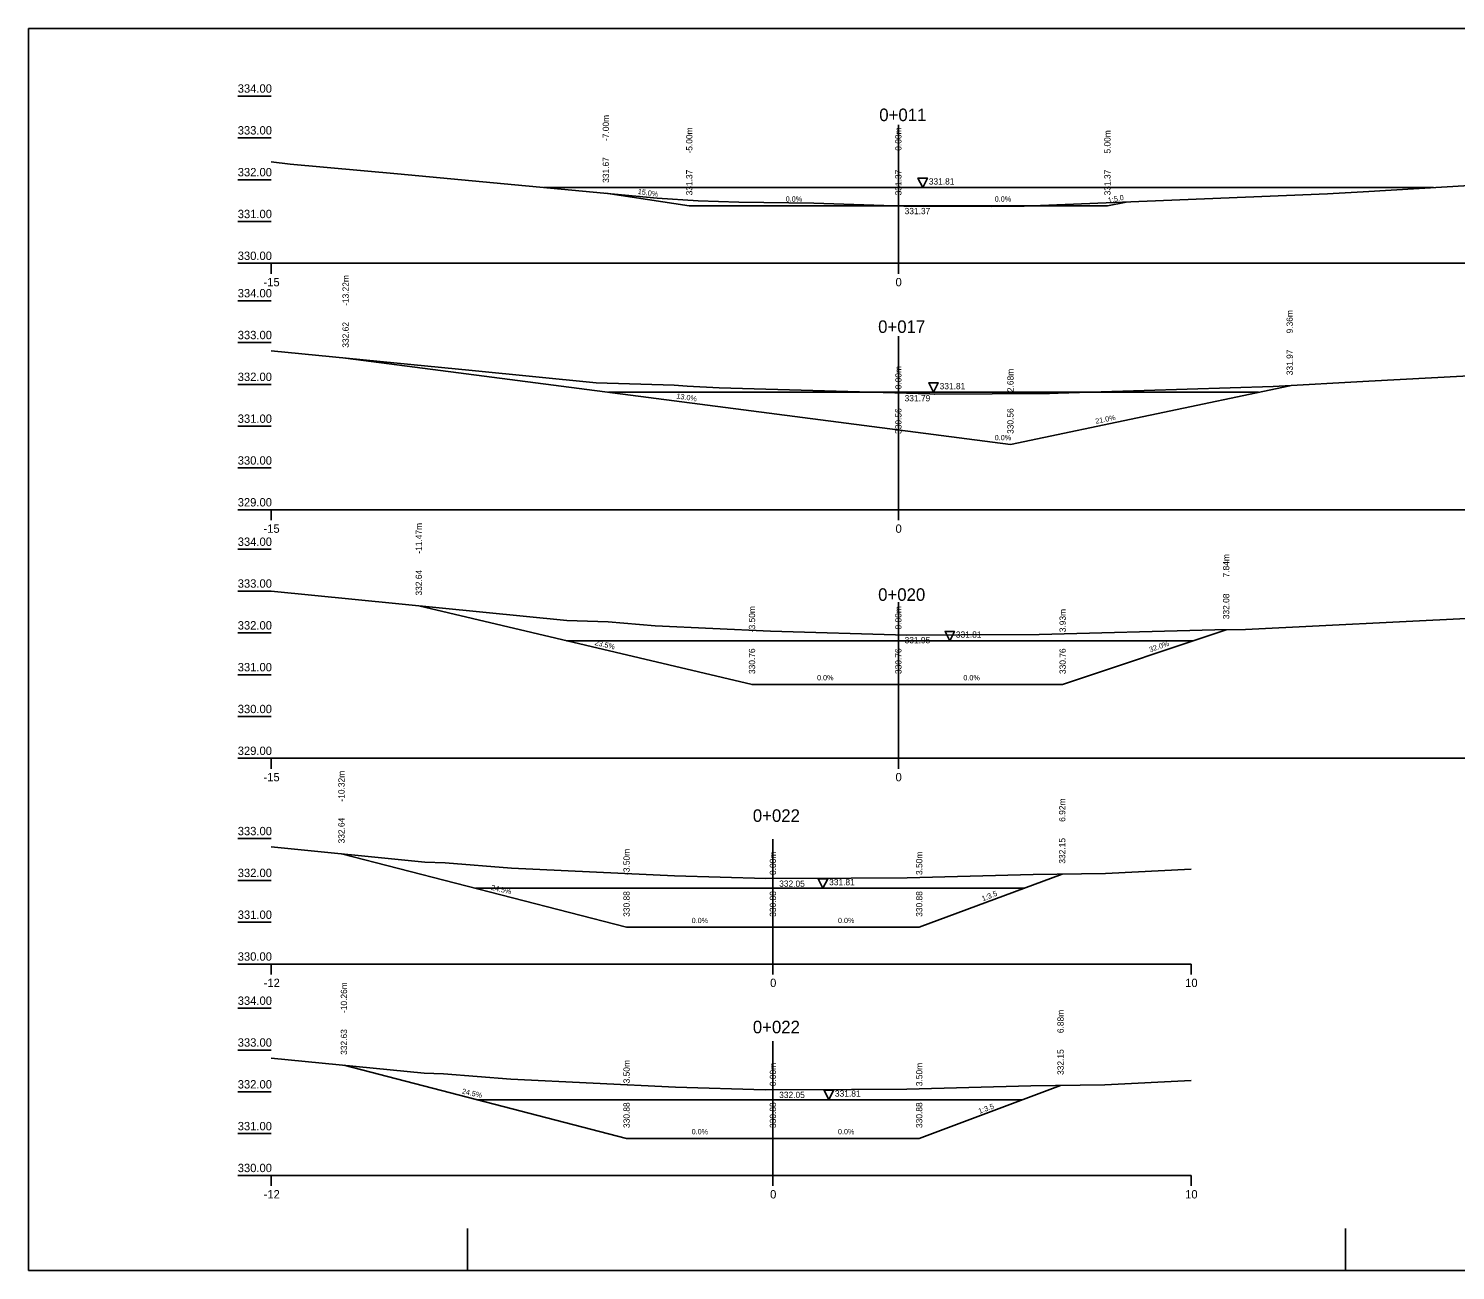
# Model space of a CAD drawing. Extents: x -557924.8 to -557872.3, y -1163725.6 to -1163695.9.
# Drawn here: x -557924.75 to -557890.63, y -1163725.55 to -1163695.85 of the extents above; entities that cross this region are included whole.
import ezdxf

# ---------------------------------------------------------------- set-up
doc = ezdxf.new("R2010")
doc.units = 0
for name, color, linetype in [('16', 7, 'Continuous'), ('21', 7, 'Continuous'), ('28', 7, 'Continuous'), ('59', 7, 'Continuous'), ('Body pricny rez', 7, 'Continuous'), ('Popis pricneho profilu', 7, 'Continuous')]:
    doc.layers.add(name, color=color, linetype=linetype)

msp = doc.modelspace()

# ---------------------------------------------------------------- linework, layer by layer
for p, q in [((-557872.255, -1163695.855), (-557924.755, -1163695.855)), ((-557924.755, -1163695.855), (-557924.755, -1163725.555)), ((-557914.255, -1163725.555), (-557914.255, -1163724.555)), ((-557893.255, -1163725.555), (-557893.255, -1163724.555)), ((-557924.755, -1163725.555), (-557872.255, -1163725.555))]:
    msp.add_line(p, q)
for points in [[(-557918.951, -1163699.04), (-557918.5, -1163699.102), (-557915.931, -1163699.332), (-557909.723, -1163699.909), (-557908.742, -1163699.977), (-557907.763, -1163700.007), (-557905.975, -1163700.03), (-557903.818, -1163700.099), (-557901.717, -1163700.109), (-557900.944, -1163700.106), (-557893.687, -1163699.806), (-557893.547, -1163699.801), (-557892.834, -1163699.759), (-557888.951, -1163699.526)], [(-557912.421, -1163699.658), (-557891.151, -1163699.658)], [(-557910.947, -1163699.795), (-557908.951, -1163700.094), (-557903.951, -1163700.094), (-557898.951, -1163700.094), (-557898.505, -1163700.005)], [(-557908.951, -1163700.094), (-557910.947, -1163699.795)], [(-557908.951, -1163700.094), (-557910.947, -1163699.795)], [(-557903.951, -1163700.094), (-557908.951, -1163700.094)], [(-557903.951, -1163700.094), (-557908.951, -1163700.094)], [(-557903.951, -1163700.094), (-557898.951, -1163700.094)], [(-557903.951, -1163700.094), (-557898.951, -1163700.094)], [(-557898.951, -1163700.094), (-557898.505, -1163700.005)], [(-557898.951, -1163700.094), (-557898.505, -1163700.005)], [(-557918.951, -1163703.563), (-557914.142, -1163704.032), (-557911.18, -1163704.326), (-557909.313, -1163704.385), (-557909.001, -1163704.41), (-557908.235, -1163704.447), (-557903.194, -1163704.592), (-557903.088, -1163704.595), (-557903.08, -1163704.595), (-557900.337, -1163704.586), (-557900.125, -1163704.577), (-557894.989, -1163704.419), (-557892.701, -1163704.285), (-557888.951, -1163704.089)], [(-557917.171, -1163703.737), (-557901.271, -1163705.8)], [(-557901.271, -1163705.8), (-557894.591, -1163704.396)], [(-557910.884, -1163704.553), (-557895.336, -1163704.553)], [(-557918.951, -1163709.313), (-557911.88, -1163710.015), (-557910.889, -1163710.046), (-557909.765, -1163710.137), (-557907.01, -1163710.268), (-557903.744, -1163710.362), (-557902.449, -1163710.356), (-557900.581, -1163710.35), (-557896.385, -1163710.235), (-557895.647, -1163710.225), (-557890.2, -1163709.956), (-557888.951, -1163709.891)], [(-557903.951, -1163711.542), (-557907.451, -1163711.542), (-557915.421, -1163709.664)], [(-557900.021, -1163711.542), (-557896.111, -1163710.231)], [(-557911.889, -1163710.496), (-557896.901, -1163710.496)], [(-557903.951, -1163711.542), (-557907.451, -1163711.542)], [(-557903.951, -1163711.542), (-557900.451, -1163711.542)], [(-557903.951, -1163711.542), (-557900.021, -1163711.542)], [(-557918.951, -1163715.425), (-557915.28, -1163715.789), (-557914.791, -1163715.805), (-557913.202, -1163715.932), (-557909.308, -1163716.118), (-557907.124, -1163716.181), (-557905.082, -1163716.172), (-557903.742, -1163716.167), (-557900.73, -1163716.085), (-557898.999, -1163716.062), (-557896.951, -1163715.961)], [(-557906.951, -1163717.347), (-557910.451, -1163717.347), (-557917.271, -1163715.592)], [(-557903.451, -1163717.347), (-557900.031, -1163716.076)], [(-557914.068, -1163716.416), (-557900.947, -1163716.416)], [(-557906.951, -1163717.347), (-557910.451, -1163717.347)], [(-557906.951, -1163717.347), (-557903.451, -1163717.347)], [(-557906.951, -1163717.347), (-557903.451, -1163717.347)], [(-557918.951, -1163720.477), (-557915.296, -1163720.839), (-557914.826, -1163720.854), (-557913.219, -1163720.983), (-557909.281, -1163721.171), (-557907.139, -1163721.233), (-557905.068, -1163721.224), (-557903.748, -1163721.219), (-557900.782, -1163721.138), (-557899.013, -1163721.114), (-557896.951, -1163721.013)], [(-557906.951, -1163722.398), (-557910.451, -1163722.398), (-557917.211, -1163720.649)], [(-557903.451, -1163722.398), (-557900.071, -1163721.129)], [(-557914.032, -1163721.472), (-557900.985, -1163721.472)], [(-557906.951, -1163722.398), (-557910.451, -1163722.398)], [(-557906.951, -1163722.398), (-557903.451, -1163722.398)], [(-557906.951, -1163722.398), (-557903.451, -1163722.398)]]:
    msp.add_lwpolyline(points)
for points in [[(-557903.369, -1163699.658), (-557903.482, -1163699.433), (-557903.257, -1163699.433)], [(-557903.11, -1163704.553), (-557903.222, -1163704.328), (-557902.997, -1163704.328)], [(-557902.722, -1163710.496), (-557902.834, -1163710.271), (-557902.609, -1163710.271)], [(-557905.754, -1163716.416), (-557905.866, -1163716.191), (-557905.641, -1163716.191)], [(-557905.614, -1163721.472), (-557905.727, -1163721.247), (-557905.502, -1163721.247)]]:
    msp.add_lwpolyline(points, close=True)
at = {"layer": '16'}
for p, q in [((-557918.951, -1163701.469), (-557888.951, -1163701.469)), ((-557918.951, -1163707.364), (-557888.951, -1163707.364)), ((-557918.951, -1163713.307), (-557888.951, -1163713.307)), ((-557918.951, -1163718.227), (-557896.951, -1163718.227)), ((-557918.951, -1163723.283), (-557896.951, -1163723.283))]:
    msp.add_line(p, q, dxfattribs=at)
at = {"layer": '21'}
for p, q in [((-557919.751, -1163697.469), (-557918.951, -1163697.469)), ((-557919.751, -1163698.469), (-557918.951, -1163698.469)), ((-557919.751, -1163699.469), (-557918.951, -1163699.469)), ((-557919.751, -1163700.469), (-557918.951, -1163700.469)), ((-557919.751, -1163701.469), (-557918.951, -1163701.469)), ((-557919.751, -1163702.364), (-557918.951, -1163702.364)), ((-557919.751, -1163703.364), (-557918.951, -1163703.364)), ((-557919.751, -1163704.364), (-557918.951, -1163704.364)), ((-557919.751, -1163705.364), (-557918.951, -1163705.364)), ((-557919.751, -1163706.364), (-557918.951, -1163706.364)), ((-557919.751, -1163707.364), (-557918.951, -1163707.364)), ((-557919.751, -1163708.307), (-557918.951, -1163708.307)), ((-557919.751, -1163709.307), (-557918.951, -1163709.307)), ((-557919.751, -1163710.307), (-557918.951, -1163710.307)), ((-557919.751, -1163711.307), (-557918.951, -1163711.307)), ((-557919.751, -1163712.307), (-557918.951, -1163712.307)), ((-557919.751, -1163713.307), (-557918.951, -1163713.307)), ((-557919.751, -1163715.227), (-557918.951, -1163715.227)), ((-557919.751, -1163716.227), (-557918.951, -1163716.227)), ((-557919.751, -1163717.227), (-557918.951, -1163717.227)), ((-557919.751, -1163718.227), (-557918.951, -1163718.227)), ((-557919.751, -1163719.283), (-557918.951, -1163719.283)), ((-557919.751, -1163720.283), (-557918.951, -1163720.283)), ((-557919.751, -1163721.283), (-557918.951, -1163721.283)), ((-557919.751, -1163722.283), (-557918.951, -1163722.283)), ((-557919.751, -1163723.283), (-557918.951, -1163723.283))]:
    msp.add_line(p, q, dxfattribs=at)
at = {"layer": '28'}
for p, q in [((-557903.951, -1163698.158), (-557903.951, -1163701.469)), ((-557903.951, -1163703.212), (-557903.951, -1163707.364)), ((-557903.951, -1163709.574), (-557903.951, -1163713.307)), ((-557906.951, -1163715.24), (-557906.951, -1163718.227)), ((-557906.951, -1163720.069), (-557906.951, -1163723.283))]:
    msp.add_line(p, q, dxfattribs=at)
at = {"layer": '59'}
for p, q in [((-557918.951, -1163701.719), (-557918.951, -1163701.469)), ((-557903.951, -1163701.719), (-557903.951, -1163701.469)), ((-557918.951, -1163707.614), (-557918.951, -1163707.364)), ((-557903.951, -1163707.614), (-557903.951, -1163707.364)), ((-557918.951, -1163713.557), (-557918.951, -1163713.307)), ((-557903.951, -1163713.557), (-557903.951, -1163713.307)), ((-557918.951, -1163718.477), (-557918.951, -1163718.227)), ((-557906.951, -1163718.477), (-557906.951, -1163718.227)), ((-557896.951, -1163718.477), (-557896.951, -1163718.227)), ((-557918.951, -1163723.533), (-557918.951, -1163723.283)), ((-557906.951, -1163723.533), (-557906.951, -1163723.283)), ((-557896.951, -1163723.533), (-557896.951, -1163723.283))]:
    msp.add_line(p, q, dxfattribs=at)

# ---------------------------------------------------------------- texts
for s, height, p in [('0+011', 0.3, (-557904.407, -1163698.069)), ('331.81', 0.15, (-557903.223, -1163699.585)), ('0+017', 0.3, (-557904.434, -1163703.134)), ('331.81', 0.15, (-557902.963, -1163704.48)), ('0+020', 0.3, (-557904.434, -1163709.541)), ('331.81', 0.15, (-557902.575, -1163710.423)), ('0+022', 0.3, (-557907.431, -1163714.827)), ('331.81', 0.15, (-557905.607, -1163716.343)), ('0+022', 0.3, (-557907.431, -1163719.883)), ('331.81', 0.15, (-557905.467, -1163721.399))]:
    msp.add_text(s, height=height).set_placement(p)
for s, rotation, p in [('1:5.0', 11.3099, (-557898.926, -1163700.026)), ('1:3.5', 22.0443, (-557901.926, -1163716.728)), ('1:3.5', 20.0786, (-557902.01, -1163721.809))]:
    msp.add_text(s, height=0.125, rotation=rotation).set_placement(p)
at = {"layer": '16'}
for s, rotation, p in [('15.0%', 351.4692, (-557910.189, -1163699.809)), ('13.0%', 351.4692, (-557909.264, -1163704.7)), ('21.0%', 11.3099, (-557899.226, -1163705.308)), ('23.5%', 347.1569, (-557911.223, -1163710.596)), ('32.0%', 18.9173, (-557897.926, -1163710.771)), ('24.5%', 347.1569, (-557913.699, -1163716.45)), ('24.5%', 347.1569, (-557914.399, -1163721.323)), ('0.0%', 360, (-557908.895, -1163722.298))]:
    msp.add_text(s, height=0.125, rotation=rotation, dxfattribs=at).set_placement(p)
for p in [(-557906.645, -1163699.994), (-557901.645, -1163699.994), (-557901.645, -1163705.7), (-557905.895, -1163711.442), (-557902.395, -1163711.442), (-557908.895, -1163717.247), (-557905.395, -1163717.247), (-557905.395, -1163722.298)]:
    msp.add_text('0.0%', height=0.125, dxfattribs=at).set_placement(p)
at = {"layer": '21'}
for s, p in [('334.00', (-557919.751, -1163697.389)), ('333.00', (-557919.751, -1163698.389)), ('332.00', (-557919.751, -1163699.389)), ('331.00', (-557919.751, -1163700.389)), ('330.00', (-557919.751, -1163701.389)), ('0', (-557904.018, -1163702.019)), ('334.00', (-557919.751, -1163702.284)), ('-15', (-557919.135, -1163702.019)), ('333.00', (-557919.751, -1163703.284)), ('332.00', (-557919.751, -1163704.284)), ('331.00', (-557919.751, -1163705.284)), ('330.00', (-557919.751, -1163706.284)), ('329.00', (-557919.751, -1163707.284)), ('-15', (-557919.135, -1163707.914)), ('0', (-557904.018, -1163707.914)), ('334.00', (-557919.751, -1163708.227)), ('333.00', (-557919.751, -1163709.227)), ('332.00', (-557919.751, -1163710.227)), ('331.00', (-557919.751, -1163711.227)), ('330.00', (-557919.751, -1163712.227)), ('329.00', (-557919.751, -1163713.227)), ('-15', (-557919.135, -1163713.857)), ('0', (-557904.018, -1163713.857)), ('333.00', (-557919.751, -1163715.147)), ('332.00', (-557919.751, -1163716.147)), ('331.00', (-557919.751, -1163717.147)), ('330.00', (-557919.751, -1163718.147)), ('-12', (-557919.131, -1163718.777)), ('0', (-557907.018, -1163718.777)), ('10', (-557897.091, -1163718.777)), ('334.00', (-557919.751, -1163719.203)), ('333.00', (-557919.751, -1163720.203)), ('332.00', (-557919.751, -1163721.203)), ('331.00', (-557919.751, -1163722.203)), ('330.00', (-557919.751, -1163723.203)), ('-12', (-557919.131, -1163723.833)), ('0', (-557907.018, -1163723.833)), ('10', (-557897.091, -1163723.833))]:
    msp.add_text(s, height=0.2, dxfattribs=at).set_placement(p)
at = {"layer": '59'}
for s, p in [('331.37', (-557903.801, -1163700.294)), ('331.79', (-557903.801, -1163704.77)), ('331.95', (-557903.801, -1163710.556)), ('332.05', (-557906.801, -1163716.38)), ('332.05', (-557906.801, -1163721.432))]:
    msp.add_text(s, height=0.15, dxfattribs=at).set_placement(p)
at = {"layer": 'Body pricny rez'}
for p in [(-557910.948, -1163699.795), (-557910.948, -1163699.795), (-557908.951, -1163700.095), (-557908.951, -1163700.095), (-557903.986, -1163700.094), (-557903.951, -1163700.095), (-557903.951, -1163700.095), (-557898.951, -1163700.095), (-557898.951, -1163700.095), (-557898.505, -1163700.006), (-557898.505, -1163700.006), (-557894.591, -1163704.397), (-557894.591, -1163704.397), (-557903.951, -1163705.801), (-557903.951, -1163705.801), (-557915.421, -1163709.664), (-557915.421, -1163709.664), (-557893.282, -1163710.109), (-557893.282, -1163710.109), (-557907.451, -1163711.543), (-557907.451, -1163711.543), (-557903.951, -1163711.543), (-557903.951, -1163711.543), (-557900.451, -1163711.543), (-557900.451, -1163711.543), (-557900.031, -1163716.076), (-557900.031, -1163716.076), (-557910.451, -1163717.347), (-557910.451, -1163717.347), (-557906.951, -1163717.347), (-557906.951, -1163717.347), (-557903.451, -1163717.347), (-557903.451, -1163717.347), (-557917.211, -1163720.65), (-557917.211, -1163720.65), (-557900.071, -1163721.129), (-557900.071, -1163721.129), (-557910.451, -1163722.399), (-557910.451, -1163722.399), (-557906.951, -1163722.399), (-557906.951, -1163722.399), (-557903.451, -1163722.399), (-557903.451, -1163722.399)]:
    msp.add_text('+', height=0.001, dxfattribs=at).set_placement(p)
at = {"layer": 'Popis pricneho profilu'}
for s, p in [('-7.00m', (-557910.872, -1163698.545)), ('-5.00m', (-557908.876, -1163698.844)), ('-0.00m', (-557903.876, -1163698.844)), ('5.00m', (-557898.876, -1163698.844)), ('331.67', (-557910.872, -1163699.545)), ('331.37', (-557908.876, -1163699.844)), ('331.37', (-557903.876, -1163699.844)), ('331.37', (-557898.876, -1163699.844)), ('-13.22m', (-557917.096, -1163702.487)), ('9.36m', (-557894.516, -1163703.146)), ('332.62', (-557917.096, -1163703.487)), ('331.97', (-557894.516, -1163704.146)), ('-0.00m', (-557903.876, -1163704.55)), ('2.68m', (-557901.196, -1163704.55)), ('330.56', (-557903.876, -1163705.55)), ('330.56', (-557901.196, -1163705.55)), ('-11.47m', (-557915.346, -1163708.414)), ('7.84m', (-557896.036, -1163708.981)), ('332.64', (-557915.346, -1163709.414)), ('332.08', (-557896.036, -1163709.981)), ('-3.50m', (-557907.376, -1163710.292)), ('-0.00m', (-557903.876, -1163710.292)), ('3.93m', (-557899.946, -1163710.292)), ('330.76', (-557907.376, -1163711.292)), ('330.76', (-557903.876, -1163711.292)), ('330.76', (-557899.946, -1163711.292)), ('-10.32m', (-557917.196, -1163714.342)), ('6.92m', (-557899.956, -1163714.826)), ('332.64', (-557917.196, -1163715.342)), ('332.15', (-557899.956, -1163715.826)), ('-3.50m', (-557910.376, -1163716.097)), ('0.00m', (-557906.876, -1163716.097)), ('3.50m', (-557903.376, -1163716.097)), ('330.88', (-557910.376, -1163717.097)), ('330.88', (-557906.876, -1163717.097)), ('330.88', (-557903.376, -1163717.097)), ('-10.26m', (-557917.136, -1163719.399)), ('6.88m', (-557899.996, -1163719.879)), ('332.63', (-557917.136, -1163720.399)), ('-3.50m', (-557910.376, -1163721.148)), ('332.15', (-557899.996, -1163720.879)), ('0.00m', (-557906.876, -1163721.148)), ('3.50m', (-557903.376, -1163721.148)), ('330.88', (-557910.376, -1163722.148)), ('330.88', (-557906.876, -1163722.148)), ('330.88', (-557903.376, -1163722.148))]:
    msp.add_text(s, height=0.15, rotation=90, dxfattribs=at).set_placement(p)

doc.saveas('drawing.dxf')
